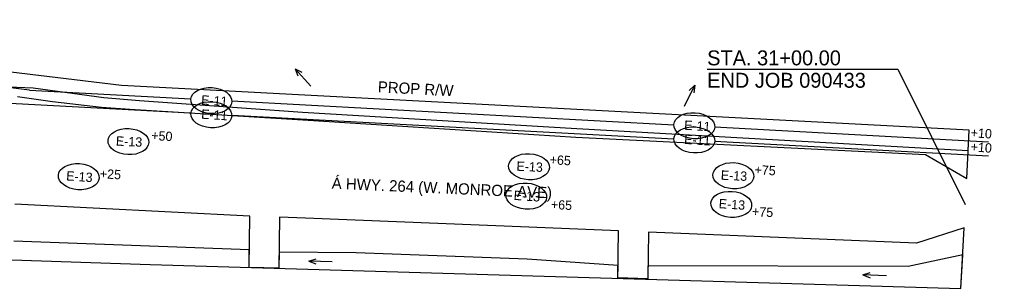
# Model space of a CAD drawing. Extents: x 670673 to 672613, y 705754 to 707185.
# Drawn here: x 672092 to 672613, y 706451 to 706595 of the extents above; entities that cross this region are included whole.
import ezdxf

# ---------------------------------------------------------------- set-up
doc = ezdxf.new("R2010")
doc.units = 0
for name, color, linetype in [('R_Draft', 7, 'Continuous'), ('R_Erosion Clearing Right', 7, 'Continuous'), ('R_Erosion Stage 1', 7, 'Continuous'), ('R_Erosion Stage 2', 7, 'Continuous'), ('R_Flow Arrows Clear and Grub', 7, 'Continuous'), ('R_No Plot', 7, 'Continuous'), ('R_Proposed Sidewalk', 7, 'Continuous')]:
    doc.layers.add(name, color=color, linetype=linetype)

# ---------------------------------------------------------------- blocks, each defined once
blk = doc.blocks.new('FLOW ARROW')
at = {"layer": 'R_Proposed Sidewalk'}
for p, q in [((-1.78, 0.09), (10.79, 0.09)), ((10.79, 0.09), (6.94, 1.49)), ((10.79, 0.09), (6.94, -1.31))]:
    blk.add_line(p, q, dxfattribs=at)

msp = doc.modelspace()

# ---------------------------------------------------------------- linework, layer by layer
at = {"layer": 'R_Draft'}
msp.add_line((672562.41, 706568.63), (672598.63, 706495.99), dxfattribs=at)
msp.add_lwpolyline([(672460.28, 706568.63), (672562.41, 706568.63)], dxfattribs=at)
at = {"layer": 'R_Erosion Clearing Right'}
for p, q in [((672060.99, 706551.75), (672183.48, 706545.15)), ((672205.72, 706543.95), (672442.48, 706531.18)), ((672464.3, 706530.01), (672611.02, 706522.1))]:
    msp.add_line(p, q, dxfattribs=at)
for centre in [(672194.57, 706544.17), (672453.38, 706530.66)]:
    msp.add_ellipse(centre, major_axis=(10.93, -0.71), ratio=0.638788, dxfattribs=at)
at = {"layer": 'R_Erosion Stage 1'}
for p, q in [((672097.09, 706557.4), (672059.07, 706561.92)), ((672097.09, 706557.4), (672183.67, 706552.73)), ((672205.58, 706551.55), (672442.36, 706538.78)), ((672464.32, 706537.6), (672611.02, 706529.69))]:
    msp.add_line(p, q, dxfattribs=at)
for centre, major_axis in [((672194.57, 706551.76), (10.93, -0.71)), ((672453.38, 706538.26), (10.93, -0.71)), ((672150.14, 706529.77), (10.94, -0.53)), ((672364.8, 706516.31), (10.94, -0.53)), ((672474.29, 706511.5), (10.94, -0.53))]:
    msp.add_ellipse(centre, major_axis=major_axis, ratio=0.638788, dxfattribs=at)
at = {"layer": 'R_Erosion Stage 2'}
for centre in [(672123.52, 706511), (672363.32, 706500.56), (672473.2, 706496.13)]:
    msp.add_ellipse(centre, major_axis=(10.93, -0.76), ratio=0.638788, dxfattribs=at)
at = {"layer": 'R_No Plot'}
for points in [[(672081.52, 706559.25), (672099, 706558.54), (672137.04, 706553.47), (672156.13, 706551.85), (672243.37, 706545.5), (672390.49, 706536.78), (672600.16, 706525.08), (672600.73, 706535.93), (672146.36, 706559.78), (671852.81, 706595.21)], [(672090.68, 706554), (672109.39, 706551.23), (672135.66, 706548.28), (672150.93, 706547.08), (672243.69, 706541.46), (672389.83, 706532.23), (672577.36, 706522.79), (672599.37, 706510), (672600.73, 706535.93), (672146.36, 706559.78), (671852.81, 706595.21)], [(671891.46, 706473.02), (672161.72, 706463.85), (672596.28, 706451.05), (672597.99, 706483.64), (672572.52, 706475.41), (672428.76, 706481.31), (672428.42, 706456.21), (672412.43, 706456.71), (672412.77, 706481.95), (672364.68, 706483.89), (672245.12, 706488.71), (672231.13, 706489.27), (672230.75, 706461.92), (672214.76, 706462.35), (672215.13, 706489.91), (672089.26, 706496.18)], [(671891.46, 706473.02), (672161.72, 706463.85), (672596.28, 706451.05), (672597.22, 706469.09), (672567.96, 706462.94), (672428.52, 706463.27), (672428.42, 706456.21), (672412.43, 706456.71), (672412.52, 706463.46), (672363.78, 706466.7), (672272.16, 706470.16), (672230.87, 706470.59), (672230.75, 706461.92), (672214.76, 706462.35), (672214.89, 706471.7), (672088.68, 706476.46)]]:
    msp.add_lwpolyline(points, dxfattribs=at)

# ---------------------------------------------------------------- block references
at = {"layer": 'R_Flow Arrows Clear and Grub'}
for p, yscale, rotation in [((672246.69, 706560.78), -0.9999999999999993, 132.87021560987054), ((672448.84, 706550.35), -0.999999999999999, 64.25690321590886), ((672257.63, 706465.29), -0.9999999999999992, 177.87947866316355), ((672554.57, 706457.91), -0.9999999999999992, 177.87947866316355)]:
    msp.add_blockref('FLOW ARROW', p, dxfattribs=dict(at, yscale=yscale, rotation=rotation))

# ---------------------------------------------------------------- texts
at = {"layer": 'R_Draft'}
for s, height, rotation, p in [('STA. 31+00.00', 8, 0, (672460.28, 706570.63)), ('END JOB 090433', 8, 0, (672460.28, 706558.63)), ('PROP R/W', 6, 356.9958, (672283.67, 706556.16)), ('Á HWY. 264 (W. MONROE AVE)', 6, 357.4635, (672259, 706504.56))]:
    msp.add_text(s, height=height, rotation=rotation, dxfattribs=at).set_placement(p)
at = {"layer": 'R_Erosion Clearing Right'}
for s, rotation, p in [('E-11', 356.2788, (672189, 706542.06)), ('E-11', 356.2788, (672447.82, 706528.56)), ('+10', 355.8145, (672601.37, 706524.59))]:
    msp.add_text(s, height=4.999, rotation=rotation, dxfattribs=at).set_placement(p)
at = {"layer": 'R_Erosion Stage 1'}
for s, rotation, p in [('E-11', 356.2788, (672189, 706549.66)), ('E-11', 356.2788, (672447.82, 706536.16)), ('+50', 356.9958, (672162.28, 706530.6)), ('+10', 355.8145, (672601.37, 706532.18)), ('E-13', 357.2101, (672143.33, 706527.65)), ('E-13', 357.2101, (672358, 706514.18)), ('+65', 356.9958, (672375.8, 706517.64)), ('E-13', 357.2101, (672467.49, 706509.37)), ('+75', 356.9958, (672485.55, 706512.26))]:
    msp.add_text(s, height=4.999, rotation=rotation, dxfattribs=at).set_placement(p)
at = {"layer": 'R_Erosion Stage 2'}
for s, rotation, p in [('E-13', 356.0298, (672116.67, 706509.01)), ('+25', 356.9958, (672134.71, 706510.13)), ('E-13', 356.0298, (672356.47, 706498.57)), ('+65', 356.9958, (672376.44, 706493.67)), ('E-13', 356.0298, (672466.36, 706494.15)), ('+75', 356.9958, (672484.24, 706489.89))]:
    msp.add_text(s, height=4.999, rotation=rotation, dxfattribs=at).set_placement(p)

doc.saveas('drawing.dxf')
